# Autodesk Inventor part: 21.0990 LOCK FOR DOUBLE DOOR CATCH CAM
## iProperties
Created: 2007-03
Part Number: 21.0990 LOCK FOR DOUBLE DOOR CATCH CAM
Document SubType Name: Modeling
Designer: Andy Moles
Material: Steel
Mass: 20.5238 g
Surface Area: 18.5486 cm^2
Volume: 2.6145 cm^3
Density: 7.85 g/cm^3
Author: Andy Moles
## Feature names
1. Extrusion1
